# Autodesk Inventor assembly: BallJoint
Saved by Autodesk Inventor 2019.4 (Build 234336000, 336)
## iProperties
Created: 2020-04
Part Number: BallJoint
Document SubType Name: Assembly
Designer: Administrator
Title: BallJoint v14
Author: Administrator
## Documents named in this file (3)
- c:\worker\convert-fusion-r03\tmp\job-1\48\output\files\ccae6ef3-9f0e-42ff-b199-3a2c6474057a\BallJoint v14_2.iam
- c:\worker\convert-fusion-r03\tmp\job-1\48\output\files\ccae6ef3-9f0e-42ff-b199-3a2c6474057a\Component1_1.ipt
- c:\worker\convert-fusion-r03\tmp\job-1\48\output\files\ccae6ef3-9f0e-42ff-b199-3a2c6474057a\Component2_1.ipt
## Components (2 placed, 2 different names)
1. Component1:1
2. Component2:1
